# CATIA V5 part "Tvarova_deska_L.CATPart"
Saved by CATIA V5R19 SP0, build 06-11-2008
Part number: Copy (1) of Tvarova_deska_P
Source: Unknown
Bounding box of the stored display mesh (mm): x -55 to 55, y -75 to 75, z -40 to 0
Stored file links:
  C:\Users\jsmid\Desktop\DP_Smidak_Forma LEGO\Tvarova_deska_L.CATPart
  C:\Users\jsmid\Desktop\DP_Smidak_Forma LEGO\DP_Smidak_Forma LEGO.CATProduct
  C:\Users\jsmid\Desktop\DP_Smidak_Forma LEGO\vtok_2.CATPart
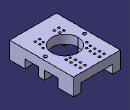
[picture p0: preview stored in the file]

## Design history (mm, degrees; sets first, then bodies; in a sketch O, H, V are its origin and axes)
Set1
  DatumSurface1: linked copy from another document
  DatumSurface2: linked copy from another document
Body1 (main body)
  Solid1 "PartBody": solid without history
  Sketch1 on face of Solid1, origin (-55, 0, 0), H (0, -1, 0), V (0, 0, 1)
    line L1 (7, -42.5964) -> (7, -28)
    point P1 (7, -28)
    reference projected arc E1 centre (15, -28) radius 8 from (15, -20) to (15, -36) ccw from edge [face of Solid1 | face of Solid1]
    reference projected arc E2 centre (15, -28) radius 8 from (15, -20) to (15, -36) ccw from edge [face of Solid1 | face of Solid1]
    line L2 (39, -42.5964) -> (39, -28)
    point P3 (39, -28)
    reference projected arc E3 centre (31, -28) radius 8 from (31, -36) to (31, -20) ccw from edge [face of Solid1 | face of Solid1]
    reference projected arc E4 centre (31, -28) radius 8 from (31, -36) to (31, -20) ccw from edge [face of Solid1 | face of Solid1]
    line L3 (39, -42.5964) -> (7, -42.5964)
    point P4 (7, -42.5964)
    line L4 (-39, -41.2278) -> (-39, -28)
    point P5 (-39, -28)
    reference projected arc E5 centre (-31, -28) radius 8 from (-31, -20) to (-31, -36) ccw from edge [face of Solid1 | face of Solid1]
    reference projected arc E6 centre (-31, -28) radius 8 from (-31, -20) to (-31, -36) ccw from edge [face of Solid1 | face of Solid1]
    line L5 (-7, -42.1799) -> (-7, -28)
    point P7 (-7, -28)
    reference projected arc E7 centre (-15, -28) radius 8 from (-15, -36) to (-15, -20) ccw from edge [face of Solid1 | face of Solid1]
    reference projected arc E8 centre (-15, -28) radius 8 from (-15, -36) to (-15, -20) ccw from edge [face of Solid1 | face of Solid1]
    line L6 (-7, -42.1799) -> (-39, -41.2278)
    line L7 (-39, -28) -> (-7, -28)
    line L8 (7, -28) -> (39, -28)
    vertical: L1 V, L2 V, L4 V, L5 V
    tangency: L1 E1, L2 E3, L4 E5, L5 E7
    coincidence: P1 E2, P3 E4, P5 E6, P7 E8, L6 P4
    horizontal: L3 H, L7 H, L8 H
  Pocket1: profile Sketch1, direction (1, 0, 0), length 20
  Sketch2 on face of Solid1, origin (55, 0, 0), H (0, 1, 0), V (0, 0, 1)
    point P1 (-39, -28)
    line L1 (-39, -28) -> (-39, -41.8597)
    point P3 (-7, -28)
    line L2 (-7, -28) -> (-7, -41.8597)
    reference projected arc E1 centre (-31, -28) radius 8 from (-31, -20) to (-31, -36) ccw from edge [face of Solid1 | face of Solid1]
    reference projected arc E2 centre (-15, -28) radius 8 from (-15, -36) to (-15, -20) ccw from edge [face of Solid1 | face of Solid1]
    reference projected arc E3 centre (-15, -28) radius 8 from (-15, -36) to (-15, -20) ccw from edge [face of Solid1 | face of Solid1]
    reference projected arc E4 centre (-31, -28) radius 8 from (-31, -20) to (-31, -36) ccw from edge [face of Solid1 | face of Solid1]
    line L3 (-39, -41.8597) -> (-7, -41.8597)
    line L4 (-39, -28) -> (-7, -28)
    point P5 (39, -28)
    line L5 (39, -28) -> (39, -42.3999)
    point P7 (7, -28)
    line L6 (7, -28) -> (7, -42.5472)
    reference projected arc E5 centre (15, -28) radius 8 from (15, -20) to (15, -36) ccw from edge [face of Solid1 | face of Solid1]
    reference projected arc E6 centre (15, -28) radius 8 from (15, -20) to (15, -36) ccw from edge [face of Solid1 | face of Solid1]
    reference projected arc E7 centre (31, -28) radius 8 from (31, -36) to (31, -20) ccw from edge [face of Solid1 | face of Solid1]
    reference projected arc E8 centre (31, -28) radius 8 from (31, -36) to (31, -20) ccw from edge [face of Solid1 | face of Solid1]
    line L7 (7, -42.5472) -> (39, -42.3999)
    line L8 (7, -28) -> (39, -28)
    vertical: L1 V, L2 V, L5 V, L6 V
    tangency: L1 E1, L2 E2, L6 E5, L5 E7
    coincidence: P3 E3, P1 E4, P7 E6, P5 E8
    horizontal: L3 H, L4 H, L8 H
  Pocket2: profile Sketch2, direction (-1, 0, 0), length 20
  Sketch3 on face of Solid1, origin (55, 0, 0), H (0, 1, 0), V (0, 0, 1)
    line L1 (7, -47.4059) -> (39, -47.4059)
    line L2 (39, -47.4059) -> (39, -20)
    line L3 (39, -20) -> (7, -20)
    line L4 (7, -20) -> (7, -47.4059)
    reference projected line E1 (39, -40) -> (39, -28) from edge [face of Solid1 | face of Pocket2 from Sketch2.L5]
    reference projected line E2 (7, -28) -> (7, -40) from edge [face of Solid1 | face of Pocket2 from Sketch2.L6]
    reference projected line E3 (15, -20) -> (31, -20) from edge [face of Solid1 | face of Solid1]
    line L5 (-39, -44.8486) -> (-7, -44.8486)
    line L6 (-7, -44.8486) -> (-7, -20)
    line L7 (-7, -20) -> (-39, -20)
    line L8 (-39, -20) -> (-39, -44.8486)
    reference projected line E4 (-7, -40) -> (-7, -28) from edge [face of Solid1 | face of Pocket2 from Sketch2.L2]
    reference projected line E5 (-39, -28) -> (-39, -40) from edge [face of Solid1 | face of Pocket2 from Sketch2.L1]
    reference projected line E6 (-31, -20) -> (-15, -20) from edge [face of Solid1 | face of Solid1]
    horizontal: L1 H, L3 H, L5 H, L7 H
    vertical: L2 V, L4 V, L6 V, L8 V
    coincidence: L2 E1, L4 E2, L3 E3, L6 E4, L8 E5, L7 E6
  Pocket3: profile Sketch3, direction (-1, 0, 0), length 20
  Sketch4 on face of Solid1, origin (-55, 0, 0), H (0, -1, 0), V (0, 0, 1)
    line L1 (7, -49.6663) -> (39, -49.6663)
    line L2 (39, -49.6663) -> (39, -20)
    line L3 (39, -20) -> (7, -20)
    line L4 (7, -20) -> (7, -49.6663)
    reference projected line E1 (31, -20) -> (15, -20) from edge [face of Solid1 | face of Solid1]
    reference projected line E2 (7, -28) -> (7, -40) from edge [face of Solid1 | face of Pocket1 from Sketch1.L1]
    reference projected line E3 (39, -40) -> (39, -28) from edge [face of Solid1 | face of Pocket1 from Sketch1.L2]
    line L5 (-39, -44.1349) -> (-7, -44.1349)
    line L6 (-7, -44.1349) -> (-7, -20)
    line L7 (-7, -20) -> (-39, -20)
    line L8 (-39, -20) -> (-39, -44.1349)
    reference projected line E4 (-15, -20) -> (-31, -20) from edge [face of Solid1 | face of Solid1]
    reference projected line E5 (-7, -40) -> (-7, -28) from edge [face of Solid1 | face of Pocket1 from Sketch1.L5]
    reference projected line E6 (-39, -28) -> (-39, -40) from edge [face of Solid1 | face of Pocket1 from Sketch1.L4]
    horizontal: L1 H, L3 H, L5 H, L7 H
    vertical: L2 V, L4 V, L6 V, L8 V
    coincidence: L3 E1, L4 E2, L2 E3, L7 E4, L6 E5, L8 E6
  Pocket4: profile Sketch4, direction (1, 0, 0), length 20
